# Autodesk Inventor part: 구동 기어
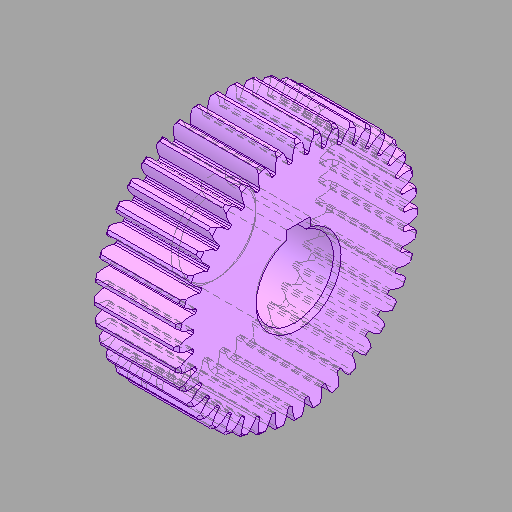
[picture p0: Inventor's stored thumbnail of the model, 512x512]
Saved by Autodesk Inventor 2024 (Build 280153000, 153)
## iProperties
Created: 2025-11
Part Number: 구동 기어
Material: 강철, 합금
Document SubType Name: Modeling
Designer: Edu09
Density: 7.73 g/cm^3
Appearance: 기본값
Author: jhkim
Sending System: Autodesk Inventor 2026
Preprocessor: ST-DEVELOPER v20.1
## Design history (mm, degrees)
feature "솔리드1"
node "솔리드2"
